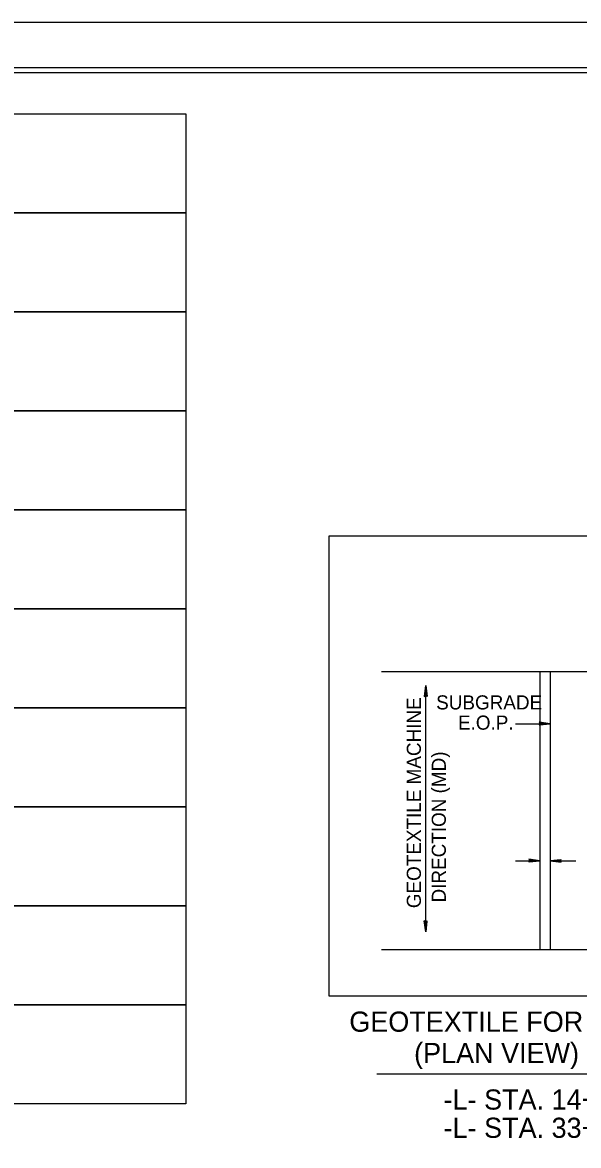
# Model space of a CAD drawing. Extents: x 1901718 to 1902220, y 193828 to 194187.
# Drawn here: x 1902073.3 to 1902100.8, y 194102.3 to 194158 of the extents above; entities that cross this region are included whole.
import ezdxf

# ---------------------------------------------------------------- set-up
doc = ezdxf.new("R2010")
doc.units = 0
for name, color, linetype in [('Old_Level_11', 7, 'Continuous'), ('Old_Level_19', 7, 'Continuous'), ('Prop Dimension Text', 7, 'Continuous'), ('Prop Lane Arrow CELL', 7, 'Continuous'), ('Prop Pavement Schedule Description CELL', 7, 'Continuous'), ('Sheet Border Standard 30in CELL', 7, 'Continuous'), ('Sheet Cutting Line CELL', 7, 'Continuous'), ('Sheet Plot Border Inside CELL', 7, 'Continuous'), ('Sheet Plot Border Outside CELL', 7, 'Continuous')]:
    doc.layers.add(name, color=color, linetype=linetype)

msp = doc.modelspace()

# ---------------------------------------------------------------- linework, layer by layer
at = {"layer": 'Old_Level_11'}
msp.add_lwpolyline([(1902088.471, 194132.556), (1902126.343, 194132.556), (1902126.343, 194109.733), (1902088.471, 194109.733)], close=True, dxfattribs=at)
at = {"layer": 'Old_Level_19'}
msp.add_lwpolyline([(1901985.367, 194153.482), (1902081.367, 194153.482), (1902081.367, 194148.573), (1901985.367, 194148.573)], close=True, dxfattribs=at)
for points in [[(1902038.276, 194143.664), (1902033.367, 194143.664), (1902033.367, 194148.573), (1902081.367, 194148.573), (1902081.367, 194143.664), (1902038.276, 194143.664), (1902038.276, 194148.573)], [(1902038.276, 194128.937), (1902033.367, 194128.937), (1902033.367, 194133.846), (1902081.367, 194133.846), (1902081.367, 194128.937), (1902038.276, 194128.937), (1902038.276, 194133.846)], [(1902038.276, 194124.028), (1902033.367, 194124.028), (1902033.367, 194128.937), (1902081.367, 194128.937), (1902081.367, 194124.028), (1902038.276, 194124.028), (1902038.276, 194128.937)], [(1902038.276, 194119.119), (1902033.367, 194119.119), (1902033.367, 194124.028), (1902081.367, 194124.028), (1902081.367, 194119.119), (1902038.276, 194119.119), (1902038.276, 194124.028)], [(1902038.276, 194114.21), (1902033.367, 194114.21), (1902033.367, 194119.119), (1902081.367, 194119.119), (1902081.367, 194114.21), (1902038.276, 194114.21), (1902038.276, 194119.119)], [(1902038.276, 194109.301), (1902033.367, 194109.301), (1902033.367, 194114.21), (1902081.367, 194114.21), (1902081.367, 194109.301), (1902038.276, 194109.301), (1902038.276, 194114.21)], [(1902038.276, 194104.392), (1902033.367, 194104.392), (1902033.367, 194109.301), (1902081.367, 194109.301), (1902081.367, 194104.392), (1902038.276, 194104.392), (1902038.276, 194109.301)]]:
    msp.add_lwpolyline(points, dxfattribs=at)
at = {"layer": 'Prop Dimension Text'}
for p, q in [((1902098.902, 194125.82), (1902098.902, 194112.026)), ((1902099.417, 194125.82), (1902099.417, 194112.026)), ((1902093.25, 194125.133), (1902093.176, 194124.588)), ((1902093.186, 194124.598), (1902093.25, 194125.133)), ((1902093.25, 194125.133), (1902093.197, 194124.609)), ((1902093.207, 194124.619), (1902093.25, 194125.133)), ((1902093.25, 194125.133), (1902093.219, 194124.629)), ((1902093.228, 194124.638), (1902093.25, 194125.133)), ((1902093.25, 194125.133), (1902093.239, 194124.649)), ((1902093.25, 194125.133), (1902093.323, 194124.588)), ((1902093.25, 194124.659), (1902093.25, 194125.133)), ((1902093.26, 194124.649), (1902093.25, 194125.133)), ((1902093.25, 194125.133), (1902093.27, 194124.638)), ((1902093.281, 194124.629), (1902093.25, 194125.133)), ((1902093.25, 194125.133), (1902093.292, 194124.619)), ((1902093.303, 194124.609), (1902093.25, 194125.133)), ((1902093.25, 194125.133), (1902093.312, 194124.598)), ((1902093.25, 194112.917), (1902093.25, 194125.133)), ((1902093.176, 194124.588), (1902093.25, 194124.659)), ((1902093.25, 194124.659), (1902093.323, 194124.588)), ((1902097.703, 194123.24), (1902099.417, 194123.24)), ((1902099.417, 194123.24), (1902098.872, 194123.314)), ((1902098.872, 194123.314), (1902098.942, 194123.24)), ((1902099.417, 194123.24), (1902098.872, 194123.167)), ((1902098.942, 194123.24), (1902098.872, 194123.167)), ((1902098.881, 194123.304), (1902099.417, 194123.24)), ((1902099.417, 194123.24), (1902098.881, 194123.178)), ((1902099.417, 194123.24), (1902098.892, 194123.293)), ((1902098.892, 194123.187), (1902099.417, 194123.24)), ((1902098.902, 194123.283), (1902099.417, 194123.24)), ((1902099.417, 194123.24), (1902098.902, 194123.198)), ((1902099.417, 194123.24), (1902098.912, 194123.271)), ((1902098.912, 194123.209), (1902099.417, 194123.24)), ((1902098.921, 194123.262), (1902099.417, 194123.24)), ((1902099.417, 194123.24), (1902098.921, 194123.22)), ((1902099.417, 194123.24), (1902098.932, 194123.251)), ((1902098.932, 194123.23), (1902099.417, 194123.24)), ((1902098.942, 194123.24), (1902099.417, 194123.24)), ((1902098.902, 194116.441), (1902098.357, 194116.515)), ((1902098.357, 194116.515), (1902098.427, 194116.441)), ((1902098.367, 194116.505), (1902098.902, 194116.441)), ((1902098.902, 194116.441), (1902098.377, 194116.494)), ((1902099.417, 194116.441), (1902099.962, 194116.514)), ((1902099.417, 194116.441), (1902099.952, 194116.504)), ((1902099.941, 194116.494), (1902099.417, 194116.441)), ((1902099.892, 194116.441), (1902099.962, 194116.514)), ((1902097.703, 194116.441), (1902098.902, 194116.441)), ((1902098.902, 194116.441), (1902098.357, 194116.368)), ((1902098.427, 194116.441), (1902098.357, 194116.368)), ((1902098.902, 194116.441), (1902098.367, 194116.379)), ((1902098.377, 194116.388), (1902098.902, 194116.441)), ((1902098.387, 194116.484), (1902098.902, 194116.441)), ((1902098.902, 194116.441), (1902098.387, 194116.399)), ((1902098.902, 194116.441), (1902098.397, 194116.473)), ((1902098.397, 194116.41), (1902098.902, 194116.441)), ((1902098.407, 194116.463), (1902098.902, 194116.441)), ((1902098.902, 194116.441), (1902098.407, 194116.421)), ((1902098.902, 194116.441), (1902098.417, 194116.452)), ((1902098.417, 194116.431), (1902098.902, 194116.441)), ((1902098.427, 194116.441), (1902098.902, 194116.441)), ((1902099.417, 194116.441), (1902099.932, 194116.484)), ((1902099.921, 194116.472), (1902099.417, 194116.441)), ((1902099.417, 194116.441), (1902099.912, 194116.462)), ((1902099.901, 194116.451), (1902099.417, 194116.441)), ((1902099.417, 194116.441), (1902100.682, 194116.441)), ((1902099.417, 194116.441), (1902099.962, 194116.367)), ((1902099.952, 194116.378), (1902099.417, 194116.441)), ((1902099.417, 194116.441), (1902099.941, 194116.388)), ((1902099.932, 194116.399), (1902099.417, 194116.441)), ((1902099.417, 194116.441), (1902099.921, 194116.41)), ((1902099.912, 194116.42), (1902099.417, 194116.441)), ((1902099.417, 194116.441), (1902099.901, 194116.43)), ((1902099.892, 194116.441), (1902099.417, 194116.441)), ((1902099.962, 194116.367), (1902099.892, 194116.441)), ((1902093.25, 194112.917), (1902093.177, 194113.463)), ((1902093.25, 194113.392), (1902093.177, 194113.463)), ((1902093.25, 194112.917), (1902093.187, 194113.453)), ((1902093.197, 194113.442), (1902093.25, 194112.917)), ((1902093.25, 194112.917), (1902093.207, 194113.432)), ((1902093.219, 194113.422), (1902093.25, 194112.917)), ((1902093.25, 194112.917), (1902093.229, 194113.413)), ((1902093.24, 194113.402), (1902093.25, 194112.917)), ((1902093.25, 194112.917), (1902093.324, 194113.463)), ((1902093.324, 194113.463), (1902093.25, 194113.392)), ((1902093.313, 194113.453), (1902093.25, 194112.917)), ((1902093.25, 194112.917), (1902093.303, 194113.442)), ((1902093.292, 194113.432), (1902093.25, 194112.917)), ((1902093.25, 194112.917), (1902093.281, 194113.422)), ((1902093.271, 194113.413), (1902093.25, 194112.917)), ((1902093.25, 194112.917), (1902093.261, 194113.402)), ((1902093.25, 194113.392), (1902093.25, 194112.917)), ((1902090.826, 194105.871), (1902124.653, 194105.871))]:
    msp.add_line(p, q, dxfattribs=at)
for points in [[(1902122.486, 194125.82), (1902106.554, 194125.82), (1902106.197, 194126.385), (1902105.971, 194125.332), (1902105.603, 194125.82), (1902091.057, 194125.82)], [(1902122.486, 194112.026), (1902106.554, 194112.026), (1902106.197, 194112.591), (1902105.971, 194111.538), (1902105.603, 194112.026), (1902091.057, 194112.026)]]:
    msp.add_lwpolyline(points, dxfattribs=at)
at = {"layer": 'Prop Pavement Schedule Description CELL'}
for points in [[(1902038.276, 194138.755), (1902033.367, 194138.755), (1902033.367, 194143.664), (1902081.367, 194143.664), (1902081.367, 194138.755), (1902038.276, 194138.755), (1902038.276, 194143.664)], [(1902038.276, 194133.846), (1902033.367, 194133.846), (1902033.367, 194138.755), (1902081.367, 194138.755), (1902081.367, 194133.846), (1902038.276, 194133.846), (1902038.276, 194138.755)]]:
    msp.add_lwpolyline(points, dxfattribs=at)
at = {"layer": 'Sheet Border Standard 30in CELL'}
msp.add_lwpolyline([(1902132.544, 194155.514), (1901982.544, 194155.514), (1901982.544, 194050.514), (1902132.544, 194050.514)], close=True, dxfattribs=at)
at = {"layer": 'Sheet Cutting Line CELL'}
msp.add_line((1902134.244, 194158.014), (1901965.844, 194158.014), dxfattribs=at)
at = {"layer": 'Sheet Plot Border Inside CELL'}
msp.add_lwpolyline([(1902133.794, 194155.769), (1901967.144, 194155.769), (1901967.144, 194050.259), (1902133.794, 194050.259)], close=True, dxfattribs=at)
at = {"layer": 'Sheet Plot Border Outside CELL'}
msp.add_lwpolyline([(1902134.244, 194158.014), (1901965.844, 194158.014), (1901965.844, 194048.014), (1902134.244, 194048.014)], close=True, dxfattribs=at)

# ---------------------------------------------------------------- texts
at = {"layer": 'Prop Dimension Text'}
for s, height, rotation, p in [('GEOTEXTILE MACHINE', 0.7, 90, (1902093.013, 194114.093)), ('DIRECTION (MD)', 0.7, 90, (1902094.249, 194114.376)), ('GEOTEXTILE FOR SUBGRADE STABILIZATION PLACEMENT', 0.99999, 360, (1902089.465, 194107.965)), ('(PLAN VIEW)', 0.99999, 360, (1902092.676, 194106.412))]:
    msp.add_text(s, height=height, rotation=rotation, dxfattribs=at).set_placement(p)
for s, p in [('SUBGRADE', (1902093.768, 194123.947)), ('E.O.P.', (1902094.85, 194122.944))]:
    msp.add_text(s, height=0.7, dxfattribs=at).set_placement(p)
at = {"layer": 'Prop Lane Arrow CELL'}
for s, p in [('-L- STA. 14+05.00 TO 32.45.00 LT/RT', (1902094.138, 194104.104)), ('-L- STA. 33+25.00 TO 55+50.00 LT/RT', (1902094.138, 194102.704))]:
    msp.add_text(s, height=0.99999, dxfattribs=at).set_placement(p)

doc.saveas('drawing.dxf')
